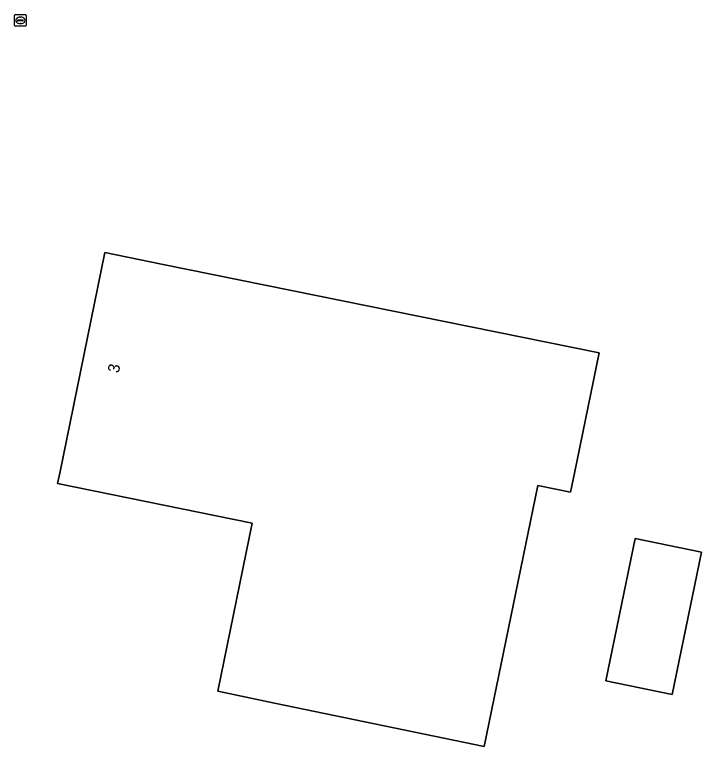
# Model space of a CAD drawing. Extents: x 157692 to 159674, y 381452 to 383291.
# Drawn here: x 158140.8 to 158200.1, y 381976.4 to 382039.6 of the extents above; entities that cross this region are included whole.
import ezdxf

# ---------------------------------------------------------------- set-up
doc = ezdxf.new("R2010")
doc.units = 0
for name, color, linetype in [('IMGEO_Erf', 7, 'Continuous'), ('IMGEO_Pand', 7, 'Continuous'), ('IMGEO_Pand_nummerreeks', 7, 'Continuous'), ('IMGEO_Rioolput', 7, 'Continuous')]:
    doc.layers.add(name, color=color, linetype=linetype)

msp = doc.modelspace()

# ---------------------------------------------------------------- linework, layer by layer
at = {"layer": 'IMGEO_Erf'}
for points in [[(158189.165, 382000), (158188.829, 381998.363), (158186.008, 381998.943), (158181.374, 381976.397), (158163.246, 381980.142), (158158.349, 381981.153), (158161.317, 381995.691), (158144.494, 381999.126), (158144.672, 382000), (158148.566, 382019.074), (158153.467, 382018.079), (158191.303, 382010.401)], [(158197.602, 381980.871), (158191.867, 381982.05), (158194.399, 381994.368), (158200.134, 381993.189)]]:
    msp.add_lwpolyline(points, close=True, dxfattribs=at)
at = {"layer": 'IMGEO_Pand'}
for points in [[(158163.246, 381980.142), (158181.374, 381976.397), (158186.008, 381998.943), (158188.829, 381998.363), (158189.165, 382000), (158191.303, 382010.401), (158153.467, 382018.079), (158148.566, 382019.074), (158144.672, 382000), (158144.494, 381999.126), (158161.317, 381995.691), (158158.349, 381981.153)], [(158197.602, 381980.871), (158200.134, 381993.189), (158194.399, 381994.368), (158191.867, 381982.05)]]:
    msp.add_lwpolyline(points, close=True, dxfattribs=at)
at = {"layer": 'IMGEO_Rioolput'}
for p, q in [((158140.779, 382038.704), (158140.779, 382039.556)), ((158140.854, 382039.63), (158141.706, 382039.63)), ((158141.038, 382039.124), (158141.038, 382039.136)), ((158141.476, 382039.087), (158141.078, 382039.087)), ((158141.081, 382039.173), (158141.479, 382039.173)), ((158141.267, 382039.41), (158141.292, 382039.41)), ((158141.522, 382039.136), (158141.522, 382039.124)), ((158141.78, 382039.556), (158141.78, 382038.704)), ((158141.706, 382038.63), (158140.854, 382038.63)), ((158141.29, 382038.85), (158141.265, 382038.85))]:
    msp.add_line(p, q, dxfattribs=at)
for points in [[(158140.779, 382038.704), (158140.779, 382039.556)], [(158140.854, 382039.63), (158141.706, 382039.63)], [(158141.78, 382039.556), (158141.78, 382038.704)], [(158141.706, 382038.63), (158140.854, 382038.63)]]:
    msp.add_lwpolyline(points, dxfattribs=at)
for centre, radius, start, end in [((158140.856, 382039.554), 0.0765, 91.55205, 178.44795), ((158140.856, 382039.554), 0.0765, 91.55205, 178.44795), ((158141.078, 382039.133), 0.0403, 85.87752, 175.75265), ((158141.075, 382039.123), 0.0366, 178.93798, 274.71019), ((158141.479, 382039.13), 0.043, 264.86636, 352.45326), ((158141.483, 382039.135), 0.0386, 1.73085, 96.63898), ((158141.704, 382039.554), 0.0765, 1.55205, 88.44795), ((158141.704, 382039.554), 0.0765, 1.55205, 88.44795), ((158140.856, 382038.706), 0.0765, 181.55205, 268.44795), ((158140.856, 382038.706), 0.0765, 181.55205, 268.44795), ((158141.704, 382038.706), 0.0765, 271.55205, 358.44795), ((158141.704, 382038.706), 0.0765, 271.55205, 358.44795)]:
    msp.add_arc(centre, radius, start, end, dxfattribs=at)
for centre, major_axis, ratio, start_param, end_param in [((158141.266, 382039.13), (-0.387, 0.002), 0.722429, 4.712389, 7.853982), ((158141.291, 382039.13), (-0.39, 0.002), 0.717154, 1.570796, 4.712389)]:
    msp.add_ellipse(centre, major_axis=major_axis, ratio=ratio, start_param=start_param, end_param=end_param, dxfattribs=at)

# ---------------------------------------------------------------- texts
at = {"layer": 'IMGEO_Pand_nummerreeks'}
msp.add_text('3', height=1, rotation=78.46149, dxfattribs=at).set_placement((158149.778, 382008.611))

doc.saveas('drawing.dxf')
